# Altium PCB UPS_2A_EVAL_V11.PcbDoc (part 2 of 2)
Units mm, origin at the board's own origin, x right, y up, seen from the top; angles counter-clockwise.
Board outline 85 x 55 mm, 4 copper layers (Top Layer, Mid1, Mid2, Bottom Layer), stack 1.572 mm thick; 131 components, 65 nets, 459 pads, 411 vias.
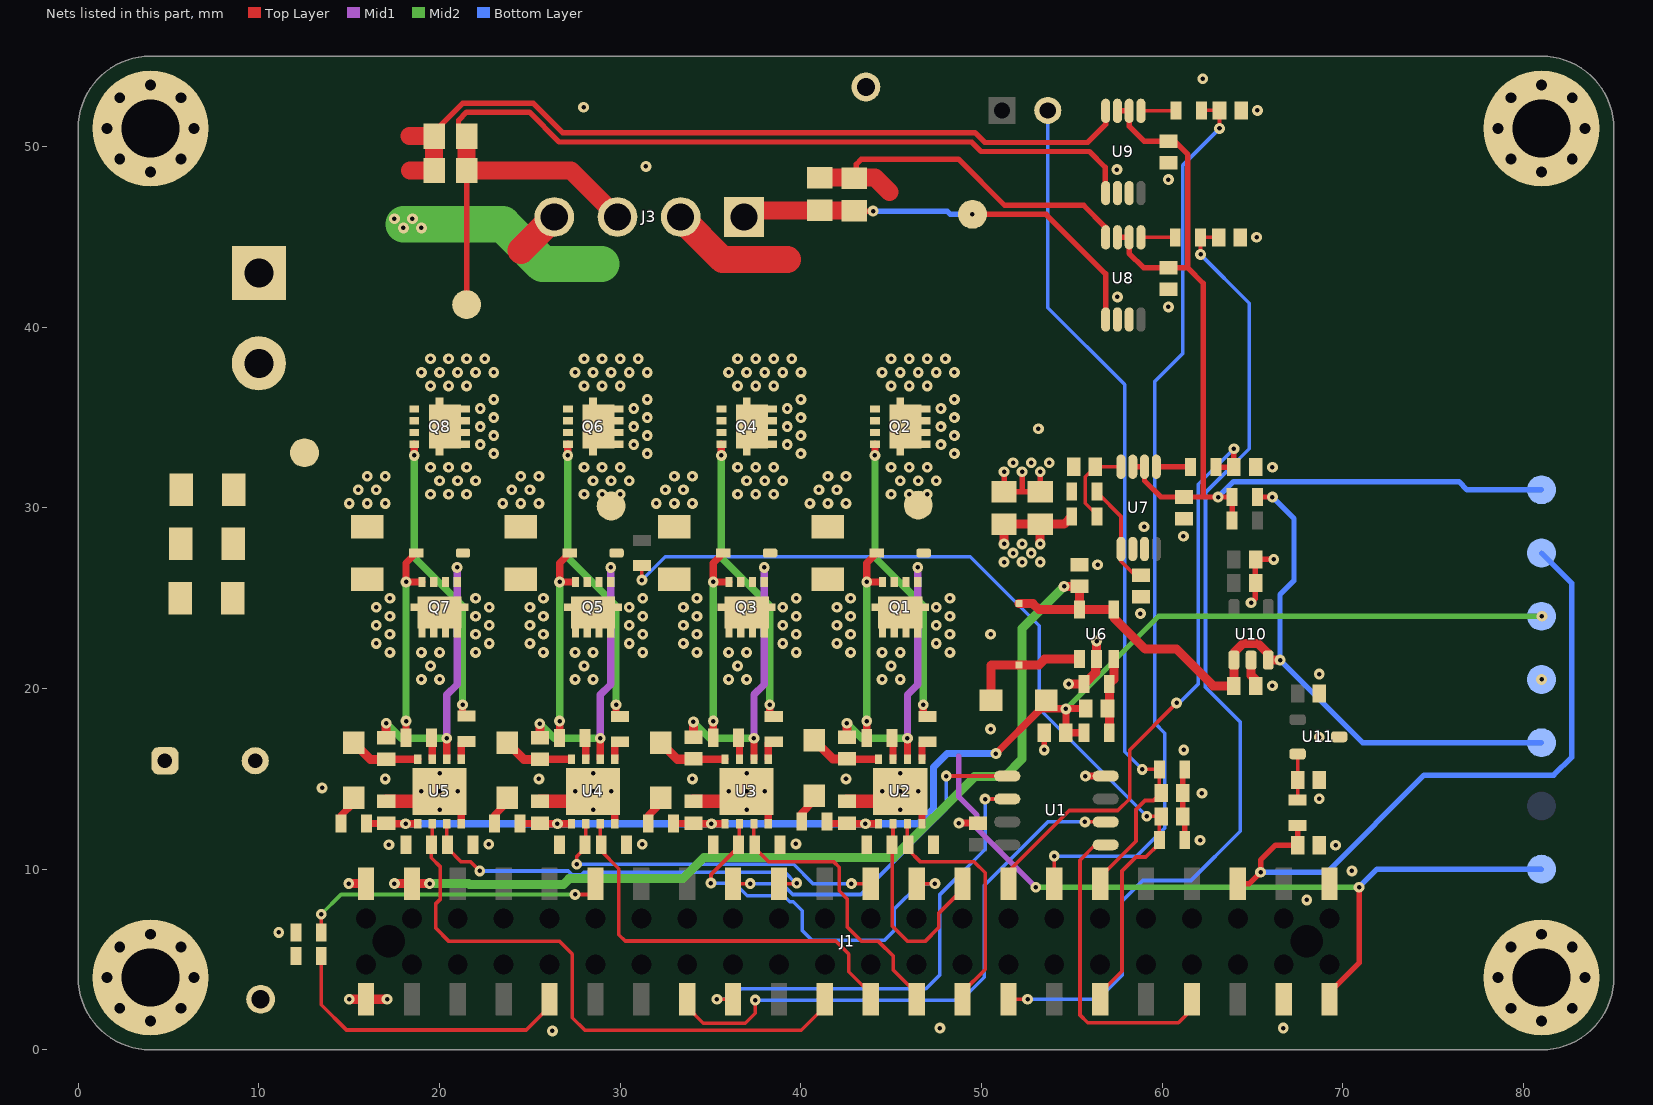
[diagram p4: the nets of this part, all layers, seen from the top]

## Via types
v1: diameter 0.6, hole 0.25, Top Layer to Bottom Layer, tented both sides, 373 vias
v2: diameter 1, hole 0.6, Top Layer to Bottom Layer, tented both sides, 32 vias
v3: diameter 0.6, hole 0.25, Top Layer to Bottom Layer, 6 vias

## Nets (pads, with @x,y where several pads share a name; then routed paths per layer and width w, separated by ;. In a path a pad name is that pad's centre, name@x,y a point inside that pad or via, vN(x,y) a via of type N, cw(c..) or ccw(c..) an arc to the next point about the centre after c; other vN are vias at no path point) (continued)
+5V: C10.2 C31.2 J1.42 L1.1 R34.1 TP2.1 U6.4 U6.5 U10.1 U10.3 | length 98.4
  Top Layer w0.3: R34.1@65.275,30.6 v1(66.1,30.6)
  Top Layer w0.5: v1(17.5,9.2) v1(19.45,9.2) ; L1.1@52.075,24.7 52.85,24.7 53.175,24.375 U6.5@55.425,24.375 ; v1@54.675,25.65 C10.2@55.425,25.65 U6.5@55.425,24.375 ; v1(66.525,21.575) U10.3@65.875,21.575 65.875,21.928 65.303,22.5 64.5,22.5 63.975,21.975 U10.1@63.975,21.575 C31.2@63.975,20.15 62.825,20.15 60.8,22.175 59.075,22.175 57.325,23.925 U6.4@57.325,24.375 U6.5@55.425,24.375
  Mid2 w0.5: v1(17.5,9.2) v1(19.45,9.2) 21.6,9.2 21.65,9.15 26.851,9.15 27.176,9.475 33.475,9.475 34.65,10.65 45.15,10.65 49.625,15.125 51.275,15.125 52.25,16.1 52.25,23.325 v1(54.575,25.65)
  Bottom Layer w0.3: v1(66.1,30.6) 67.3,29.4 67.3,25.975 66.525,25.2 v1(66.525,21.575) 71.1,17 TP2.1@81,17
+USH: C23.2 C27.1 C29.2 R33.2 R34.2 TP5.1 U7.6 U7.7 U8.6 U8.7 U9.6 U9.7 | length 56.2
  Top Layer w0.3: U8.7@57.525,44.975 U8.6@58.175,44.975 58.175,44.091 58.966,43.3 C27.1@60.35,43.3 61.4,43.3 ; U9.7@57.525,51.975 U9.6@58.175,51.975 58.175,51.125 59,50.3 C29.2@60.35,50.3 60.675,50.3 61.425,49.55 61.425,43.325 ; U7.7@58.375,32.275 U7.6@59.025,32.275 59.025,31.5 59.925,30.6 C23.2@61.2,30.6 62.275,30.6 ; R33.2@63.875,29.3 R34.2@63.875,30.6 v1(63.1,30.6) 62.275,30.6 ; 61.4,43.3 61.425,43.325 ; 61.4,43.3 61.425,43.275 ; 61.425,43.275 61.425,43.325 ; 61.425,43.275 62.275,42.425 62.275,30.6
  Bottom Layer w0.3: v1(63.1,30.6) 63.95,31.45 76.425,31.45 76.875,31 TP5.1@81,31
+V_GD: C11.2 C12.2 C13.2 C14.2 C15.2 C16.2 D5.1 R5.1 R10.1 R15.1 R20.1 R23.2 TP3.1 U2.1 U3.1 U4.1 U5.1 | length 84.6
  Top Layer w0.4: R20.1@15.95,12.525 C16.2@17.05,12.525 ; C16.2@17.175,12.515 v1(18.125,12.515) U5.1@18.8,12.515 ; R15.1@24.45,12.525 C15.2@25.55,12.525 ; C15.2@25.675,12.515 v1(26.525,12.515) U4.1@27.3,12.515 ; R10.1@32.95,12.525 C14.2@34.05,12.525 ; C14.2@34.175,12.515 v1(35.05,12.515) U3.1@35.8,12.515 ; R5.1@41.475,12.525 C13.2@42.55,12.525 ; C13.2@42.675,12.515 v1(43.575,12.515) U2.1@44.3,12.515 ; v1(50.8,16.4) 53.275,18.875 v1(54.675,18.875) C12.2@54.675,17.55 R23.2@55.675,17.55 ; D5.1@53.575,19.35 54.025,18.9 C11.2@55.775,18.9
  Mid2 w0.3: v1(54.675,18.875) 59.8,24 v1(81.025,24)
  Bottom Layer w0.4: v1(18.125,12.515) v1(26.525,12.515) v1(35.05,12.515) v1(43.575,12.515) 46.515,12.515 47.35,13.35 47.35,15.64 48.11,16.4 v1(50.8,16.4)
C\S\_\C\H\1\: J1.7 U1.1 | length 17.6
  Top Layer w0.2: U1.1@56.875,11.345 56.295,11.345 55.45,10.5 55.45,1.925 55.875,1.5 60.9,1.5 61.65,2.25 J1.7@61.65,2.8
EXTREF_2V5: C36.2 J1.6 R41.2 TP11.1 | length 37.7
  Top Layer w0.3: J1.6@64.19,9.615 J1.6@64.19,9.2 64.825,9.2 v1(65.45,9.825) 65.45,10.5 66.275,11.325 C36.2@67.2,11.325 ; C36.2@67.5,11.325 R41.2@67.5,12.425
  Bottom Layer w0.3: v1(65.45,9.825) 69.125,9.825 74.5,15.2 81.675,15.2 82.675,16.2 82.675,25.825 TP11.1@81,27.5
GND: C1.1 C2.1 C3.1 C4.1 C5.1 C10.1 C12.1 C13.1 C14.1 C15.1 C16.1 C21.1 C22.1 C23.1 C24.1 C25.1 C26.1 C27.2 C28.1 C29.1 C30.1 C31.1 C32.1 C33.1 C34.1 C35.1 C36.1 J1.2 J1.3 J1.43 J1.44 J2.1 MP1.1 MP2.1 MP3.1 MP4.1 R1.1 R2.1 R3.1 R4.1 R8.1 R9.1 R13.1 R14.1 R18.1 R19.1 R24.1 R25.1 R26.1 R28.1 R31.1 R32.1 TP_GND1.1 TP_GND2.1 TP_GND3.1 U1.4 U2.4 U2.9 U3.4 U3.9 U4.4 U4.9 U5.4 U5.9 U6.2 U7.2 U7.3 U8.2 U8.3 U9.2 U9.3 U10.2 U11.3 | length 44.2
  Top Layer w0.3: v1(20,14.3) U5.9@21.2,13.1 ; v1(28.5,14.3) U4.9@29.7,13.1 ; v1(37,14.3) U3.9@38.2,13.1 ; v1(51.25,32) R25.1@51.25,30.9 52.25,30.9 ; v1(52.25,32) 52.25,30.9 ; v1(53.25,32) R26.1@53.25,30.9 52.25,30.9 ; v1(53.475,16.6) C12.1@53.475,17.55 ; R31.1@61.25,11.625 61.25,12.825 C25.1@61.15,12.925 C26.1@61.15,14.225 61.15,15.425 R32.1@61.25,15.525 ; v1(64.925,24.75) 65.15,24.975 65.15,27.15 C33.1@65.175,27.15 v1(66.175,27.15) ; C31.1@65.175,20.15 C31.1@65.175,20.475
  Top Layer w0.4: U5.4@21.2,12.515 U5.9@21.2,13.1 ; U4.4@29.7,12.515 U4.9@29.7,13.1 ; U3.4@38.2,12.515 U3.9@38.2,13.1 ; U2.4@46.7,12.49 U2.4@46.7,12.515 U2.9@46.7,13.075 ; v1(48.75,12.55) C5.1@49.8,12.55 ; v1(55.75,15.155) U1.4@56.875,15.155
  Top Layer w0.5: v1(14.975,9.2) J1.44@15.93,9.2 ; v1(15,2.8) v1(17.1,2.8) ; v1(54.825,20.25) R24.1@55.675,20.25 56.325,20.9 56.325,21.625 U6.2@56.375,21.625 v1(56.375,22.625) ; U10.2@64.925,21.575 64.925,20.725 C31.1@65.175,20.475
  Top Layer w0.75: C16.1@17.05,13.75 19.45,13.75 v1(20,14.3) ; C15.1@25.55,13.75 27.95,13.75 v1(28.5,14.3) ; C14.1@34.05,13.75 36.45,13.75 v1(37,14.3) ; C13.1@42.55,13.75 U2.9@44.45,13.75 ; U2.9@44.95,13.75 U2.9@44.45,13.75 ; U2.9@45,14.3 U2.9@44.45,13.75
  other v1: 26.25,1.05 47.7,1.2 66.7,1.2 11.1,6.5 68,8.3 70.5,9.9 69.6,11.325 62.1,11.6 20,13.3 28.5,13.3 37,13.3 45.5,13.3 68.7,13.9 62.2,14.2 19,14.3 21,14.3 27.5,14.3 29.5,14.3 36,14.3 38,14.3 44.5,14.3 45.5,14.3 46.5,14.3 13.5,14.5 17,15 25.5,15 34,15 42.5,15 20,15.3 28.5,15.3 37,15.3 45.5,15.3 61.2,16.6 68.7,17.3 50.5,17.75 66.1,20.15 81,20.5 68.7,20.8 50.5,23 58.8,24.15 56.425,26.85 61.175,28.425 59,28.95 66.1,32.25 51.75,32.5 52.75,32.5 53.75,32.5 53.15,34.375 60.35,41.125 57.525,41.675 65.225,44.975 60.35,48.175 57.5,48.725 65.275,52 27.975,52.175 62.25,53.75
  other v2: 4,1.6 81,1.6 2.303,2.303 5.697,2.303 79.303,2.303 82.697,2.303 1.6,4 6.4,4 78.6,4 83.4,4 2.303,5.697 5.697,5.697 79.303,5.697 82.697,5.697 4,6.4 81,6.4 4,48.6 81,48.6 2.303,49.303 5.697,49.303 79.303,49.303 82.697,49.303 1.6,51 6.4,51 78.6,51 83.4,51 2.303,52.697 5.697,52.697 79.303,52.697 82.697,52.697 4,53.4 81,53.4
  other v3: 17.2,11.35 22.725,11.375 31.225,11.375 39.725,11.4 31.425,48.9
I_SUM: C17.1 C18.1 C19.1 C20.1 Q2.1 Q2.2 Q2.3 Q4.1 Q4.2 Q4.3 Q6.1 Q6.2 Q6.3 Q8.1 Q8.2 Q8.3 R25.2 R26.2 R27.1 | length 6.1
  Top Layer w0.5: v1(51.25,28) R25.2@51.25,29.1 R26.2@53.25,29.1 ; v1(53.25,28) R26.2@53.25,29.1 ; R27.1@55,29.525 54.575,29.1 R26.2@53.25,29.1
  other v1: 51.25,27 52.25,27 53.25,27 51.75,27.5 52.75,27.5 52.25,28 15,30.25 16,30.25 17,30.25 23.5,30.25 24.5,30.25 25.5,30.25 32,30.25 33,30.25 34,30.25 40.5,30.25 41.5,30.25 42.5,30.25 15.5,31 16.5,31 24,31 25,31 32.5,31 33.5,31 41,31 42,31 16,31.75 17,31.75 24.5,31.75 25.5,31.75 33,31.75 34,31.75 41.5,31.75 42.5,31.75
NetC6_1: C6.1 D1.1 U2.8 | length 4
  Top Layer w0.4: C6.1@42.55,16.1 42.565,16.085 U2.8@44.3,16.085
  Top Layer w0.5: D1.1@40.75,17.125 41.775,16.1 C6.1@42.55,16.1
NetC6_2: C6.2 D6.2 Q1.1 Q1.2 Q1.3 Q2.5 Q2.6 Q2.7 Q2.8 Q2.9 R35.1 R36.1 TP6.1 U2.6 U8.8 | length 35.7
  Top Layer w0.3: R35.1@43.07,48.825 43.07,49.02 43.35,49.3 48.725,49.3 51.275,46.75 55.65,46.75 56.875,45.525 U8.8@56.875,44.975
  Top Layer w0.4: U2.6@45.9,16.085 v1(45.9,17.25)
  Top Layer w0.5: C6.2@42.55,17.3 v1(42.55,18.075)
  Top Layer w1: R36.1@41.05,48.275 44.1,48.275 44.9,47.475
  Mid1 w0.4: v1(45.9,17.25) 45.9,19.65 46.475,20.225 v1(46.475,26.7)
  Mid2 w0.4: v1(42.55,18.075) 43.375,17.25 v1(45.9,17.25)
  other v1: 45,30.75 46,30.75 47,30.75 45.5,31.5 46.5,31.5 47.5,31.5 45,32.25 46,32.25 47,32.25 48.5,33 47.75,33.5 48.5,34 47.75,34.5 48.5,35 47.75,35.5 48.5,36 45,36.75 46,36.75 47,36.75 44.5,37.5 45.5,37.5 46.5,37.5 47.5,37.5 48.5,37.5 45,38.25 46,38.25 47,38.25 48,38.25
NetC7_1: C7.1 D2.1 U3.8 | length 3.9
  Top Layer w0.4: C7.1@34.065,16.085 U3.8@35.8,16.085
  Top Layer w0.5: D2.1@32.25,17 33.165,16.085 C7.1@34.065,16.085
NetC7_2: C7.2 D7.2 J3.2 Q3.1 Q3.2 Q3.3 Q4.5 Q4.6 Q4.7 Q4.8 Q4.9 U3.6 | length 22.3
  Top Layer w0.4: U3.6@37.4,16.085 v1(37.4,17.25)
  Top Layer w0.5: C7.2@34.05,17.3 v1(34.05,18.15)
  Top Layer w1.5: J3.2@33.35,46.1 33.35,46.056 35.656,43.75 39.25,43.75
  Mid1 w0.4: v1(37.4,17.25) 37.4,19.65 37.975,20.225 v1(37.975,26.7)
  Mid2 w0.4: v1(34.05,18.15) 34.95,17.25 v1(37.4,17.25)
  other v1: 36.5,30.75 37.5,30.75 38.5,30.75 37,31.5 38,31.5 39,31.5 36.5,32.25 37.5,32.25 38.5,32.25 40,33 39.25,33.5 40,34 39.25,34.5 40,35 39.25,35.5 40,36 36.5,36.75 37.5,36.75 38.5,36.75 36,37.5 37,37.5 38,37.5 39,37.5 40,37.5 36.5,38.25 37.5,38.25 38.5,38.25 39.5,38.25
NetC8_1: C8.1 D3.1 U4.8 | length 3.9
  Top Layer w0.2: C8.1@25.55,16.075 C8.1@25.56,16.085
  Top Layer w0.4: C8.1@25.56,16.085 U4.8@27.3,16.085
  Top Layer w0.5: D3.1@23.75,17 24.675,16.075 C8.1@25.55,16.075
NetC8_2: C8.2 D8.2 Q5.1 Q5.2 Q5.3 Q6.5 Q6.6 Q6.7 Q6.8 Q6.9 R37.1 R38.1 TP8.1 U4.6 U9.8 | length 71.9
  Top Layer w0.3: R38.1@19.7,50.575 19.7,50.807 21.293,52.4 25.182,52.4 26.807,50.775 49.632,50.775 50.182,50.225 55.875,50.225 56.875,51.225 U9.8@56.875,51.975
  Top Layer w0.4: U4.6@28.9,16.085 v1(28.9,17.25)
  Top Layer w0.5: C8.2@25.55,17.275 v1(25.55,18.05)
  Top Layer w1: 18.35,50.575 R38.1@19.7,50.575 R37.1@19.7,48.675 18.375,48.675
  Mid1 w0.4: v1(28.9,17.25) 28.9,19.65 29.475,20.225 v1(29.475,26.7) v1@29.5,26.7
  Mid2 w0.4: v1(25.55,18.05) 26.35,17.25 v1(28.9,17.25)
  Mid2 w2: v1@18,45.7 23.497,45.7 25.697,43.5 28.975,43.5
  other v1: 28,30.75 29,30.75 30,30.75 28.5,31.5 29.5,31.5 30.5,31.5 28,32.25 29,32.25 30,32.25 31.5,33 30.75,33.5 31.5,34 30.75,34.5 31.5,35 30.75,35.5 31.5,36 28,36.75 29,36.75 30,36.75 27.5,37.5 28.5,37.5 29.5,37.5 30.5,37.5 31.5,37.5 28,38.25 29,38.25 30,38.25 31,38.25 18,45.5 19,45.5 17.5,46 18.5,46
NetC9_1: C9.1 D4.1 U5.8 | length 3.9
  Top Layer w0.4: C9.1@17.05,16.075 17.06,16.085 U5.8@18.8,16.085
  Top Layer w0.5: D4.1@15.25,17 16.175,16.075 C9.1@17.05,16.075
NetC9_2: C9.2 D9.2 J3.4 Q7.1 Q7.2 Q7.3 Q8.5 Q8.6 Q8.7 Q8.8 Q8.9 U5.6 | length 18.1
  Top Layer w0.4: U5.6@20.4,16.085 v1(20.4,17.25)
  Top Layer w0.5: C9.2@17.05,17.275 v1(17.05,18.075)
  Top Layer w1.5: 24.5,44.25 J3.4@26.35,46.1
  Mid1 w0.4: v1(20.4,17.25) 20.4,19.65 20.975,20.225 v1(20.975,26.7) v1@20.975,26.8
  Mid2 w0.4: v1(17.05,18.075) 17.875,17.25 v1(20.4,17.25)
  other v1: 19.5,30.75 20.5,30.75 21.5,30.75 20,31.5 21,31.5 22,31.5 19.5,32.25 20.5,32.25 21.5,32.25 23,33 22.25,33.5 23,34 22.25,34.5 23,35 22.25,35.5 23,36 19.5,36.75 20.5,36.75 21.5,36.75 19,37.5 20,37.5 21,37.5 22,37.5 23,37.5 19.5,38.25 20.5,38.25 21.5,38.25 22.5,38.25
NetC11_1: C11.1 R23.1 R24.2 U6.3 | length 4.2
  Top Layer w0.5: R23.1@57.075,17.55 R24.2@57.075,20.25 57.325,20.5 U6.3@57.325,21.625
NetC21_2: C21.2 R27.2 U7.8 | length 4.7
  Top Layer w0.2: R27.2@56.4,29.525 56.4,29.6 55.75,30.25 55.75,31.725 C21.2@56.3,32.275 U7.8@57.725,32.275
NetC22_2: C22.2 R28.2 U7.1 | length 5.8
  Top Layer w0.2: R28.2@56.4,30.9 56.4,30.85 57.725,29.525 U7.1@57.725,27.725 57.725,27.052 58.502,26.275 C22.2@58.825,26.275
NetC24_2: C24.2 J1.16 R29.2 | length 33
  Top Layer w0.2: J1.16@51.49,9.2 51.49,9.884 53.771,12.165 53.776,12.165 54.861,13.25 57.55,13.25 58.2,13.9 58.2,16.6 v1(60.8,19.2)
  Top Layer w0.3: R29.2@62.975,32.25 C24.2@63.975,32.25 v1(63.975,33.275)
  Bottom Layer w0.2: v1@60.8,19.175 v1@60.812,19.188 ; v1(60.8,19.2) 60.95,19.2 62,20.25 62,31.3 v1(63.975,33.275)
NetC25_2: C25.2 J1.11 R30.1 R31.2 | length 50.6
  Top Layer w0.2: v1(31.2,26) R30.1@31.2,26.8 ; J1.11@56.57,2.8 56.57,3.145 57.775,4.35 57.775,9.9 58.55,10.675 59.1,10.675 59.85,11.425 R31.2@59.85,11.625 59.85,12.825 C25.2@59.95,12.925 v1(59.15,12.925)
  Bottom Layer w0.2: v1(31.2,26) 32.5,27.3 49.375,27.3 53.2,23.475 53.2,18.875 v1(59.15,12.925)
NetC26_2: C26.2 J1.12 J4.2 R32.2 | length 47.6
  Top Layer w0.2: J1.12@56.57,9.2 56.57,9.57 58.55,11.55 58.55,13.3 59.05,13.8 59.525,13.8 C26.2@59.95,14.225 59.85,14.325 R32.2@59.85,15.525 v1(58.9,15.525)
  Bottom Layer w0.2: J4.2@53.67,52 53.67,41.08 57.925,36.825 57.925,16.5 v1(58.9,15.525)
NetC28_2: C28.2 J1.15 R39.2 | length 55.9
  Top Layer w0.2: J1.15@51.49,2.8 v1(52.55,2.8) ; v1(62.125,44.025) R39.2@62.125,44.975 C28.2@63.125,44.975
  Bottom Layer w0.2: v1(52.55,2.8) 56.45,2.8 57.8,4.15 57.8,8.25 58.925,9.375 61.6,9.375 64.325,12.1 64.325,18.15 62.4,20.075 62.4,30.85 64.825,33.275 64.825,41.325 v1(62.125,44.025)
NetC30_2: C30.2 J1.14 R40.2 | length 50.7
  Top Layer w0.2: v1(54.025,10.725) J1.14@54.03,9.2 ; R40.2@62.175,52 C30.2@63.175,52 v1(63.175,51)
  Bottom Layer w0.2: v1(54.025,10.725) 58.6,10.725 60.15,12.275 60.15,17.525 59.6,18.075 59.6,37 61.15,38.55 61.15,48.975 v1(63.175,51)
NetC35_2: C35.2 R41.1 U11.2 | length 2.5
  Top Layer w0.2: R41.1@67.5,13.825 U11.2@67.5,16.375
NetD1_2: D1.2 R5.2 | length 1.7
  Top Layer w0.4: R5.2@40.05,12.65 40.05,13.1 40.75,13.8 D1.2@40.75,14.075
NetD2_2: D2.2 R10.2 | length 1.7
  Top Layer w0.2: D2.2@32.25,13.65 D2.2@32.25,13.95
  Top Layer w0.4: R10.2@31.55,12.525 31.55,12.95 D2.2@32.25,13.65
NetD3_2: D3.2 R15.2 | length 1.7
  Top Layer w0.4: R15.2@23.05,12.525 23.05,13 23.775,13.725 D3.2@23.775,13.95
NetD4_2: D4.2 R20.2 | length 1.7
  Top Layer w0.4: R20.2@14.55,12.525 14.55,12.975 15.25,13.675 D4.2@15.25,13.95
NetD5_2: D5.2 L1.2 U6.1 | length 7
  Top Layer w0.5: D5.2@50.525,19.35 50.525,21.275 50.55,21.3 L1.2@52.075,21.3 53.175,21.3 53.5,21.625 U6.1@55.425,21.625
NetD6_1: D6.1 Q1.4 R6.2 | length 11.4
  Top Layer w0.4: R6.2@43.65,17.25 v1(43.65,18.2) ; D6.1@44.2,27.5 43.65,26.95 v1(43.65,25.9) Q1.4@44.525,25.9
  Mid2 w0.4: v1(43.65,18.2) v1(43.65,25.9)
NetD7_1: D7.1 Q3.4 R11.2 | length 11.5
  Top Layer w0.4: R11.2@35.15,17.275 v1(35.15,18.2) ; D7.1@35.7,27.5 35.15,26.95 v1(35.15,25.9) Q3.4@36.025,25.9
  Mid2 w0.4: v1@35.06,18.2 v1(35.15,18.2) v1(35.15,25.9) ; v1@35.085,18.175 v1@35.125,18.175
NetD8_1: D8.1 Q5.4 R16.2 | length 11.4
  Top Layer w0.4: R16.2@26.65,17.25 v1(26.65,18.2) ; D8.1@27.2,27.5 26.65,26.95 v1(26.65,25.9) Q5.4@27.525,25.9
  Mid2 w0.4: v1(26.65,18.2) v1(26.65,25.9)
NetD9_1: D9.1 Q7.4 R21.2 | length 11.3
  Top Layer w0.4: R21.2@18.15,17.275 v1(18.15,18.2) ; D9.1@18.7,27.5 18.15,26.95 v1(18.15,25.9) Q7.4@19.025,25.9
  Mid2 w0.4: v1(18.15,18.2) v1(18.15,25.9)
NetJ1_17: J1.17 R4.2 U2.3 | length 13.8
  Top Layer w0.2: U2.3@45.9,12.515 45.9,11.4 R4.2@45.95,11.35 45.95,11.075 46.625,10.4 49.6,10.4 50.2,9.8 50.2,4.45 48.95,3.2 J1.17@48.95,2.8
NetJ1_18: J1.18 R3.2 U2.2 | length 12.3
  Top Layer w0.2: U2.2@45.1,12.49 45.1,11.4 R3.2@45.05,11.35 45.05,6.875 45.925,6 46.875,6 47.625,6.75 47.625,7.55 48.95,8.875 J1.18@48.95,9.2 J1.18@48.95,9.65
NetJ1_19: J1.19 R9.2 U3.3 | length 16.1
  Top Layer w0.2: U3.3@37.4,12.515 37.4,11.4 R9.2@37.45,11.35 37.45,11.175 38.225,10.4 41.834,10.4 42.125,10.109 42.125,8.8 42.575,8.35 42.575,6.8 43.375,6 44.3,6 45.125,5.175 45.125,4.4 46.41,3.115 J1.19@46.41,2.8
NetJ1_20: J1.20 R8.2 U3.2 | length 21.3
  Top Layer w0.2: v1(35.025,9.225) 35.025,9.7 36.55,11.225 R8.2@36.55,11.35 36.6,11.4 U3.2@36.6,12.515 ; J1.20@46.41,9.2 v1(47.425,9.2)
  Bottom Layer w0.2: v1(35.025,9.225) 36.326,9.225 37.026,8.526 39.062,8.526 39.388,8.2 39.575,8.2 40.075,7.7 40.075,6.6 40.6,6.075 44.65,6.075 45.175,6.6 45.175,7.8 46.575,9.2 v1(47.425,9.2)
NetJ1_21: J1.21 R14.2 U4.3 | length 22.7
  Top Layer w0.2: U4.3@28.9,12.515 28.9,11.4 R14.2@28.95,11.35 28.95,11 29.925,10.025 29.925,6.375 30.275,6.025 41.925,6.025 42.65,5.3 42.65,4.325 43.87,3.105 J1.21@43.87,2.8
NetJ1_22: J1.22 R13.2 U4.2 | length 19.2
  Top Layer w0.2: v1(27.6,10.275) 27.6,10.7 28.05,11.15 R13.2@28.05,11.35 28.1,11.4 U4.2@28.1,12.515 ; v1(42.8,9.2) J1.22@43.87,9.2
  Bottom Layer w0.2: v1(27.6,10.275) 39.6,10.275 40.675,9.2 v1(42.8,9.2)
NetJ1_23: J1.23 R18.2 U5.2 | length 33
  Top Layer w0.2: U5.2@19.6,12.515 19.6,11.4 R18.2@19.55,11.35 19.55,10.625 20.05,10.125 20.05,8.35 19.8,8.1 19.8,6.725 20.525,6 26.65,6 27.35,5.3 27.35,1.775 28.05,1.075 40.025,1.075 41.33,2.38 J1.23@41.33,2.8
NetJ1_26: J1.26 R19.2 U5.3 | length 22.6
  Top Layer w0.2: U5.3@20.4,12.515 20.4,11.4 R19.2@20.45,11.35 20.45,11.15 21.2,10.4 21.725,10.4 v1(22.225,9.9) ; J1.26@38.79,9.2 v1@39.75,9.2
  Bottom Layer w0.2: v1(22.225,9.9) 27.126,9.9 27.351,9.675 27.849,9.675 27.999,9.825 39.125,9.825 39.725,9.225 v1(39.777,9.225)
NetJ3_1: J3.1 R35.2 R36.2 TP7.1 U8.1 | length 24.4
  Top Layer w0.3: R35.2@42.95,46.45 42.975,46.425 v3(44,46.425) ; v1(49.5,46.25) 53.575,46.25 56.875,42.95 U8.1@56.875,40.425
  Top Layer w1: J3.1@36.85,46.1 37.2,46.45 R35.2@42.95,46.45
  Bottom Layer w0.3: J3.1@36.85,46.1 J3.1@37,46.25 ; v3(44,46.425) 48.1,46.425 48.275,46.25 v1(49.5,46.25)
NetJ3_3: J3.3 R37.2 R38.2 TP9.1 U9.1 | length 58.5
  Top Layer w0.3: TP9.1@21.5,41.25 R37.2@21.5,48.675 ; R38.2@21.5,50.575 21.05,51.025 21.05,51.45 21.5,51.9 24.975,51.9 26.625,50.25 49.45,50.25 49.975,49.725 55.975,49.725 56.85,48.85 56.85,47.45 U9.1@56.875,47.425
  Top Layer w1: R38.2@21.5,50.575 R37.2@21.5,48.675 27.275,48.675 J3.3@29.85,46.1
NetQ2_4: Q2.4 R7.2 | length 16.2
  Top Layer w0.4: v1(44.1,32.9) Q2.4@44.1,33.525 ; R7.2@46.775,18.45 v1(46.775,19.1)
  Mid2 w0.4: v1(44.1,32.9) 44.1,27.25 46.775,24.575 v1(46.775,19.1)
NetQ4_4: Q4.4 R12.2 | length 16.2
  Top Layer w0.4: v1(35.6,32.9) Q4.4@35.6,33.525 ; R12.2@38.275,18.45 v1(38.275,19.1)
  Mid2 w0.4: v1(35.6,32.9) 35.6,27.25 38.275,24.575 v1(38.275,19.1)
NetQ6_4: Q6.4 R17.2 | length 16.2
  Top Layer w0.4: v1(27.1,32.9) Q6.4@27.1,33.525 ; R17.2@29.775,18.45 v1(29.775,19.1)
  Mid2 w0.4: v1@27.1,32.938 v1(27.1,32.9) 27.1,27.25 29.775,24.575 v1(29.775,19.1)
NetQ8_4: Q8.4 R22.2 | length 16.2
  Top Layer w0.4: v1(18.6,32.9) Q8.4@18.6,33.525 ; R22.2@21.275,18.45 v1(21.275,19.1)
  Mid2 w0.4: v1@18.6,32.938 v1(18.6,32.9) 18.6,27.25 21.275,24.575 v1(21.275,19.1)
NetR6_1: R6.1 U2.7 | length 1.1
  Top Layer w0.4: U2.7@45.1,16.085 R6.1@45.1,17.2
NetR7_1: R7.1 U2.5 | length 0.9
  Top Layer w0.4: U2.5@46.7,16.085 R7.1@46.7,16.975
NetR11_1: R11.1 U3.7 | length 1.1
  Top Layer w0.4: U3.7@36.6,16.085 R11.1@36.6,17.225
NetR12_1: R12.1 U3.5 | length 0.9
  Top Layer w0.4: U3.5@38.2,16.085 R12.1@38.2,16.975
NetR16_1: R16.1 U4.7 | length 0.8
  Top Layer w0.4: U4.7@28.1,16.085 R16.1@28.1,16.9
NetR17_1: R17.1 U4.5 | length 0.9
  Top Layer w0.4: U4.5@29.7,16.085 R17.1@29.7,16.975
NetR21_1: R21.1 U5.7 | length 1.2
  Top Layer w0.4: U5.7@19.6,16.085 R21.1@19.6,17.275
NetR22_1: R22.1 U5.5 | length 0.9
  Top Layer w0.4: U5.5@21.2,16.085 R22.1@21.2,16.975
NetR29_1: R29.1 U7.5 | length 1.9
  Top Layer w0.3: U7.5@59.675,32.275 61.55,32.275 R29.1@61.575,32.25
NetR39_1: R39.1 U8.5 | length 1.9
  Top Layer w0.2: U8.5@58.825,44.975 R39.1@60.725,44.975
NetR40_1: R40.1 U9.5 | length 2
  Top Layer w0.2: U9.5@58.825,51.975 R40.1@60.75,51.975
  Top Layer w0.3: R40.1@60.75,51.975 R40.1@60.775,52
PWM_H_IDLE: J1.34 R2.2 | length 17.1
  Top Layer w0.2: R2.2@13.45,6.5 v1(13.45,7.5) ; v1(27.5,8.6) 28.325,8.6 28.63,8.905 J1.34@28.63,9.2
  Mid2 w0.2: v1(13.45,7.5) 14.55,8.6 v1(27.5,8.6)
PWM_L_IDLE: J1.35 R1.2 | length 16.9
  Top Layer w0.2: R1.2@13.45,5.2 13.45,2.5 14.85,1.1 24.8,1.1 26.09,2.39 J1.35@26.09,2.8
SPI2_SCK: J1.27 U1.6 | length 25.8
  Top Layer w0.2: v1(35.35,2.8) J1.27@36.25,2.8 ; v1@50.2,13.885 U1.6@51.425,13.885
  Bottom Layer w0.2: v1(35.35,2.8) 36.125,2.8 36.7,3.375 46.925,3.375 47.7,4.15 47.7,8.6 50.2,11.1 v1(50.2,13.875)
SPI2_SDI: J1.29 U1.2 | length 31.7
  Top Layer w0.2: J1.29@33.71,2.8 33.71,2.365 34.6,1.475 36.925,1.475 37.475,2.025 v1@37.475,2.475 ; v1(55.725,12.615) U1.2@56.875,12.615
  Bottom Layer w0.2: v1(37.475,2.75) 48.875,2.75 50.15,4.025 50.15,9.1 53.665,12.615 v1(55.725,12.615)
SPI2_SDO: J1.28 U1.5 | length 19.4
  Top Layer w0.2: J1.28@36.25,9.2 v1(37.2,9.2) ; v1(48.05,15.155) U1.5@51.425,15.155
  Bottom Layer w0.2: v1(37.2,9.2) 38.954,9.2 39.554,8.6 43.325,8.6 48.05,13.325 v1(48.05,15.155) v1@48.05,15.35
VM: C1.2 C2.2 C3.2 C4.2 C17.2 C18.2 C19.2 C20.2 J1.1 J2.2 Q1.5 Q1.6 Q1.7 Q1.8 Q1.9 Q3.5 Q3.6 Q3.7 Q3.8 Q3.9 Q5.5 Q5.6 Q5.7 Q5.8 Q5.9 Q7.5 Q7.6 Q7.7 Q7.8 Q7.9 TP1.1 TP4.1 | length 44.3
  Top Layer w0.3: J1.1@69.27,2.8 69.27,3.174 70.9,4.804 v1(70.9,9)
  Mid1 w0.3: 48.75,16.25 48.75,14 49.75,13 49.75,12.25 v1(53,9)
  Mid2 w0.3: v1(53,9) v1(70.9,9)
  Bottom Layer w0.3: v1(70.9,9) 71.9,10 TP4.1@81,10
  other v1: 19,20.5 20,20.5 27.5,20.5 28.5,20.5 36,20.5 37,20.5 44.5,20.5 45.5,20.5 19.5,21.25 28,21.25 36.5,21.25 45,21.25 17.25,22 19,22 20,22 22,22 25.75,22 27.5,22 28.5,22 31.25,22 34.25,22 36,22 37,22 39.75,22 42.75,22 44.5,22 45.5,22 48.25,22 16.5,22.5 22.75,22.5 25,22.5 30.5,22.5 33.5,22.5 39,22.5 42,22.5 47.5,22.5 17.25,23 22,23 25.75,23 31.25,23 34.25,23 39.75,23 42.75,23 48.25,23 16.5,23.5 22.75,23.5 25,23.5 30.5,23.5 33.5,23.5 39,23.5 42,23.5 47.5,23.5 17.25,24 22,24 25.75,24 31.25,24 34.25,24 39.75,24 42.75,24 48.25,24 16.5,24.5 22.75,24.5 25,24.5 30.5,24.5 33.5,24.5 39,24.5 42,24.5 47.5,24.5 17.25,25 22,25 25.75,25 31.25,25 34.25,25 39.75,25 42.75,25 48.25,25
pads on no net: J1.0 J1.4 J1.5 J1.8 J1.9 J1.10 J1.13 J1.24 J1.25 J1.30 J1.31 J1.32 J1.33 J1.36 J1.37 J1.38 J1.39 J1.40 J1.41 U7.4 U8.4 U9.4 U10.4

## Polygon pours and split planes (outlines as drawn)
VM on Bottom Layer "VM_bot1" (solid, remove dead copper, pour order 333): 49.025,16 49.025,27.25 13.5,27.25 13.5,40.25 7.25,40.25 7.25,11.5 12.75,11.5 12.75,16
GND on Bottom Layer "GND-bot-last" (solid, remove dead copper, pour order 341): 85,0.025 0,0.025 0,55 85,55
NetC9_2 on Bottom Layer "NetC5_2" (solid, pour order 334): 18,27.5 18,44 26.25,44 26.25,27.5
NetC7_2 on Bottom Layer "NetC3_2" (solid, pour order 336): 35,44 43.25,44 43.25,27.7 35,27.7
NetC6_2 on Bottom Layer "NetC2_2" (solid, pour order 339): 43.5,45.25 50.75,45.25 50.75,27.75 43.5,27.75
NetC8_2 on Bottom Layer "NetC4_2" (solid, pour order 335): 26.5,44 34.75,44 34.75,27.5 26.5,27.5
NetC6_2 on Mid2 "NetC2_2" (solid, pour order 331): 44,44.5 50.75,44.5 50.75,26.5 44,26.5
NetC7_2 on Mid2 "NetC3_2" (solid, pour order 330): 35.5,44.5 43.75,44.5 43.75,26.5 35.5,26.5
NetC8_2 on Mid2 "NetC4_2" (solid, pour order 329): 27,44.5 35.25,44.5 35.25,26.5 31.3,26.5 27,26.5
NetC9_2 on Mid2 "NetC5_2" (solid, remove dead copper, pour order 328): 18,26.5 18,44.5 26.7,44.5 26.7,40.9 26.7,26.5
GND on Mid2 "GND-mid2-last" (solid, remove dead copper, pour order 332): 85,0 0,0 0,55 85,55
NetC6_2 on Mid1 "NetC2_2" (solid, pour order 325): 43.25,44 50.75,44 50.75,29.25 43.25,29.25
NetC7_2 on Mid1 "NetC3_2" (solid, pour order 324): 34.75,44 43,44 43,29.25 34.75,29.25
NetC8_2 on Mid1 "NetC4_2" (solid, pour order 323): 26.25,44 34.5,44 34.5,29.5 26.25,29.5
NetC9_2 on Mid1 "NetC5_2" (solid, pour order 322): 18,27.5 18,44 26,44 26,27.5
VM on Mid1 "VM_Mid1" (solid, pour order 320): 49,15.5 49,26 14.25,26 14.25,40.25 7.25,40.25 7.25,11.5 14.25,11.5 14.25,15.5
GND on Mid1 "GND-mid1-last" (solid, remove dead copper, pour order 326): 84.9,0 -0.1,0 -0.1,55 84.9,55
I_SUM on Mid1 "I_SUM_Mid1" (solid, pour order 321): 43.25,32 43.25,29.25 54.25,29.25 54.25,26.25 14.5,26.25 14.5,32.25 17.8,32.25 17.8,29.25 23,29.25 23,32.25 26,32.25 26,29.25 31.535,29.25 31.535,32 34.5,32 34.5,29.25 40.035,29.25 40.035,32
I_SUM on Top Layer "I_SUM_SENSE" (solid, pour order 308): 50.454,29.9 54.15,29.9 54.15,25.505 50.45,25.495
I_SUM on Top Layer "I_SUM_X1" (solid, pour order 310): 40,32.25 40.75,33 40.75,34.25 43,36.5 44.25,36.5 44.25,33 43,33 43,27.75 40,27.75
NetC8_2 on Top Layer "NetC4_2-TopSense" (solid, pour order 309): 16.95,51.5 19.375,51.5 19.375,45 16.93,45
I_SUM on Top Layer "I_SUM_Y2" (solid, pour order 313): 14.5,33.5 15.25,34.25 17.5,36.5 18.75,36.5 18.75,33 17.5,33 17.5,27.75 14.5,27.75
GND on Top Layer "GND-top-last" (solid, remove dead copper, pour order 319): 85,0 0,0 0,55 85,55
NetC9_2 on Top Layer "OUT_Y2" (solid, pour order 317): 17.5,24.75 17.5,47.8 26.25,47.8 26.25,30.5 22.75,30.5 22.75,24.75
NetC8_2 on Top Layer "OUT_Y1" (solid, pour order 316): 26.25,24.75 26.25,46.5 34.525,46.5 34.525,30.725 31.25,30.725 31.25,24.75
NetC7_2 on Top Layer "OUT_X2" (solid, pour order 315): 39.75,30.5 43,30.5 43,45.25 34.75,45.25 34.75,24.75 39.75,24.75
NetC6_2 on Top Layer "OUT_X1" (solid, remove dead copper, pour order 314): 48.475,48.725 50.214,46.986 50.25,45.1 50.25,24.75 43.25,24.75 43.25,48.725
VM on Top Layer "VM_TOP" (solid, pour order 318): 49,16.35 49,27.5 14.25,27.5 14.25,40.25 7.25,40.25 7.25,11.5 12.5,11.5 12.5,16.35
I_SUM on Top Layer "I_SUM_Y1" (solid, pour order 312): 23,32.25 23.75,33 23.75,34.25 26,36.5 27.25,36.5 27.25,33 26,33 26,27.75 23,27.75
I_SUM on Top Layer "I_SUM_X2" (solid, pour order 311): 31.5,32.25 32.25,33 32.25,34.25 34.5,36.5 35.75,36.5 35.75,33 34.5,33 34.5,27.75 31.5,27.75
no net on Top Overlay "line" (solid, pour order 308): 79.825,0 80.625,35.125 81.375,35.125 82.25,-0.075

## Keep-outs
Keep-Out Layer:
  lines w0.5: 0,4 ccw(c4,4) 4,0 ; 0,51 cw(c4,51) 4,55 ; 81,0 ccw(c81,4) 85,4 ; 81,55 cw(c81,51) 85,51 ; 0,0 0,55 85,55 85,0 0,0

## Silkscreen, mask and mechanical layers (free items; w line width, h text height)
Top Overlay:
  drawing of 56 lines, arcs and shapes, not listed
  text "STEPPER" at 46,42.25 h1.2 r180
  text "Y2" at 27.25,40.75 h1.5 r90
  text "3-PHASE" at 46.5,39.525 h1.2 r180
  text "W Y1" at 30.75,38.25 h1.5 r90
  text "U X1" at 37.75,38.25 h1.5 r90
  text "V X2" at 34.05,38.225 h1.5 r90
  text "TMC-UPS-2/24-EVAL v1.1" at 84.05,8.9 h1.2 r90
Bottom Overlay:
  drawing of 38 lines, arcs and shapes, not listed
  text "Universal Power / Stage 2/24 - EVAL /  / Interface: / Inverter PWM /  / Voltage: / 5...28V /  / Phase Current: / 2A /  / www.trinamic.com" at 56.4,40.825 h1.2 r90
PCB Outline:
  the board outline again, w0.05
Top Assembly:
  lines w0.2: 19.275,10.45 19.675,10.05 19.675,3.25 ; 21.625,10.525 22.25,9.9 22.25,3.375 ; 24.75,3.2 24.75,9.925 25.5,10.675 25.5,11.725 ; 27.4,3.15 27.4,10.375 ; 29.675,10.4 29.825,10.25 29.825,3.275 ; 34.1,11.9 34.1,10.675 34.925,9.85 34.925,3.375 ; 36.8,10.575 37.525,9.85 37.525,2.4 ; 39.3,10.55 40.05,9.8 40.05,2.5 ; 44.625,10.5 45.125,10 45.125,2.5 ; 47,10.475 47.725,9.75 47.725,2.425 ; 52.45,27.8 52.775,28.125 ; 54.25,31.75 54.5,31.5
